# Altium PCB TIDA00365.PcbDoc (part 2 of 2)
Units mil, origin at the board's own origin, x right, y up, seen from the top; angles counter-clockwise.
Board outline 2520 x 2690 mil, 4 copper layers (Top Layer, Mid Layer, GND Layer, Bottom Layer), stack 69.2 mil thick; 171 components, 86 nets, 427 pads, 370 vias.
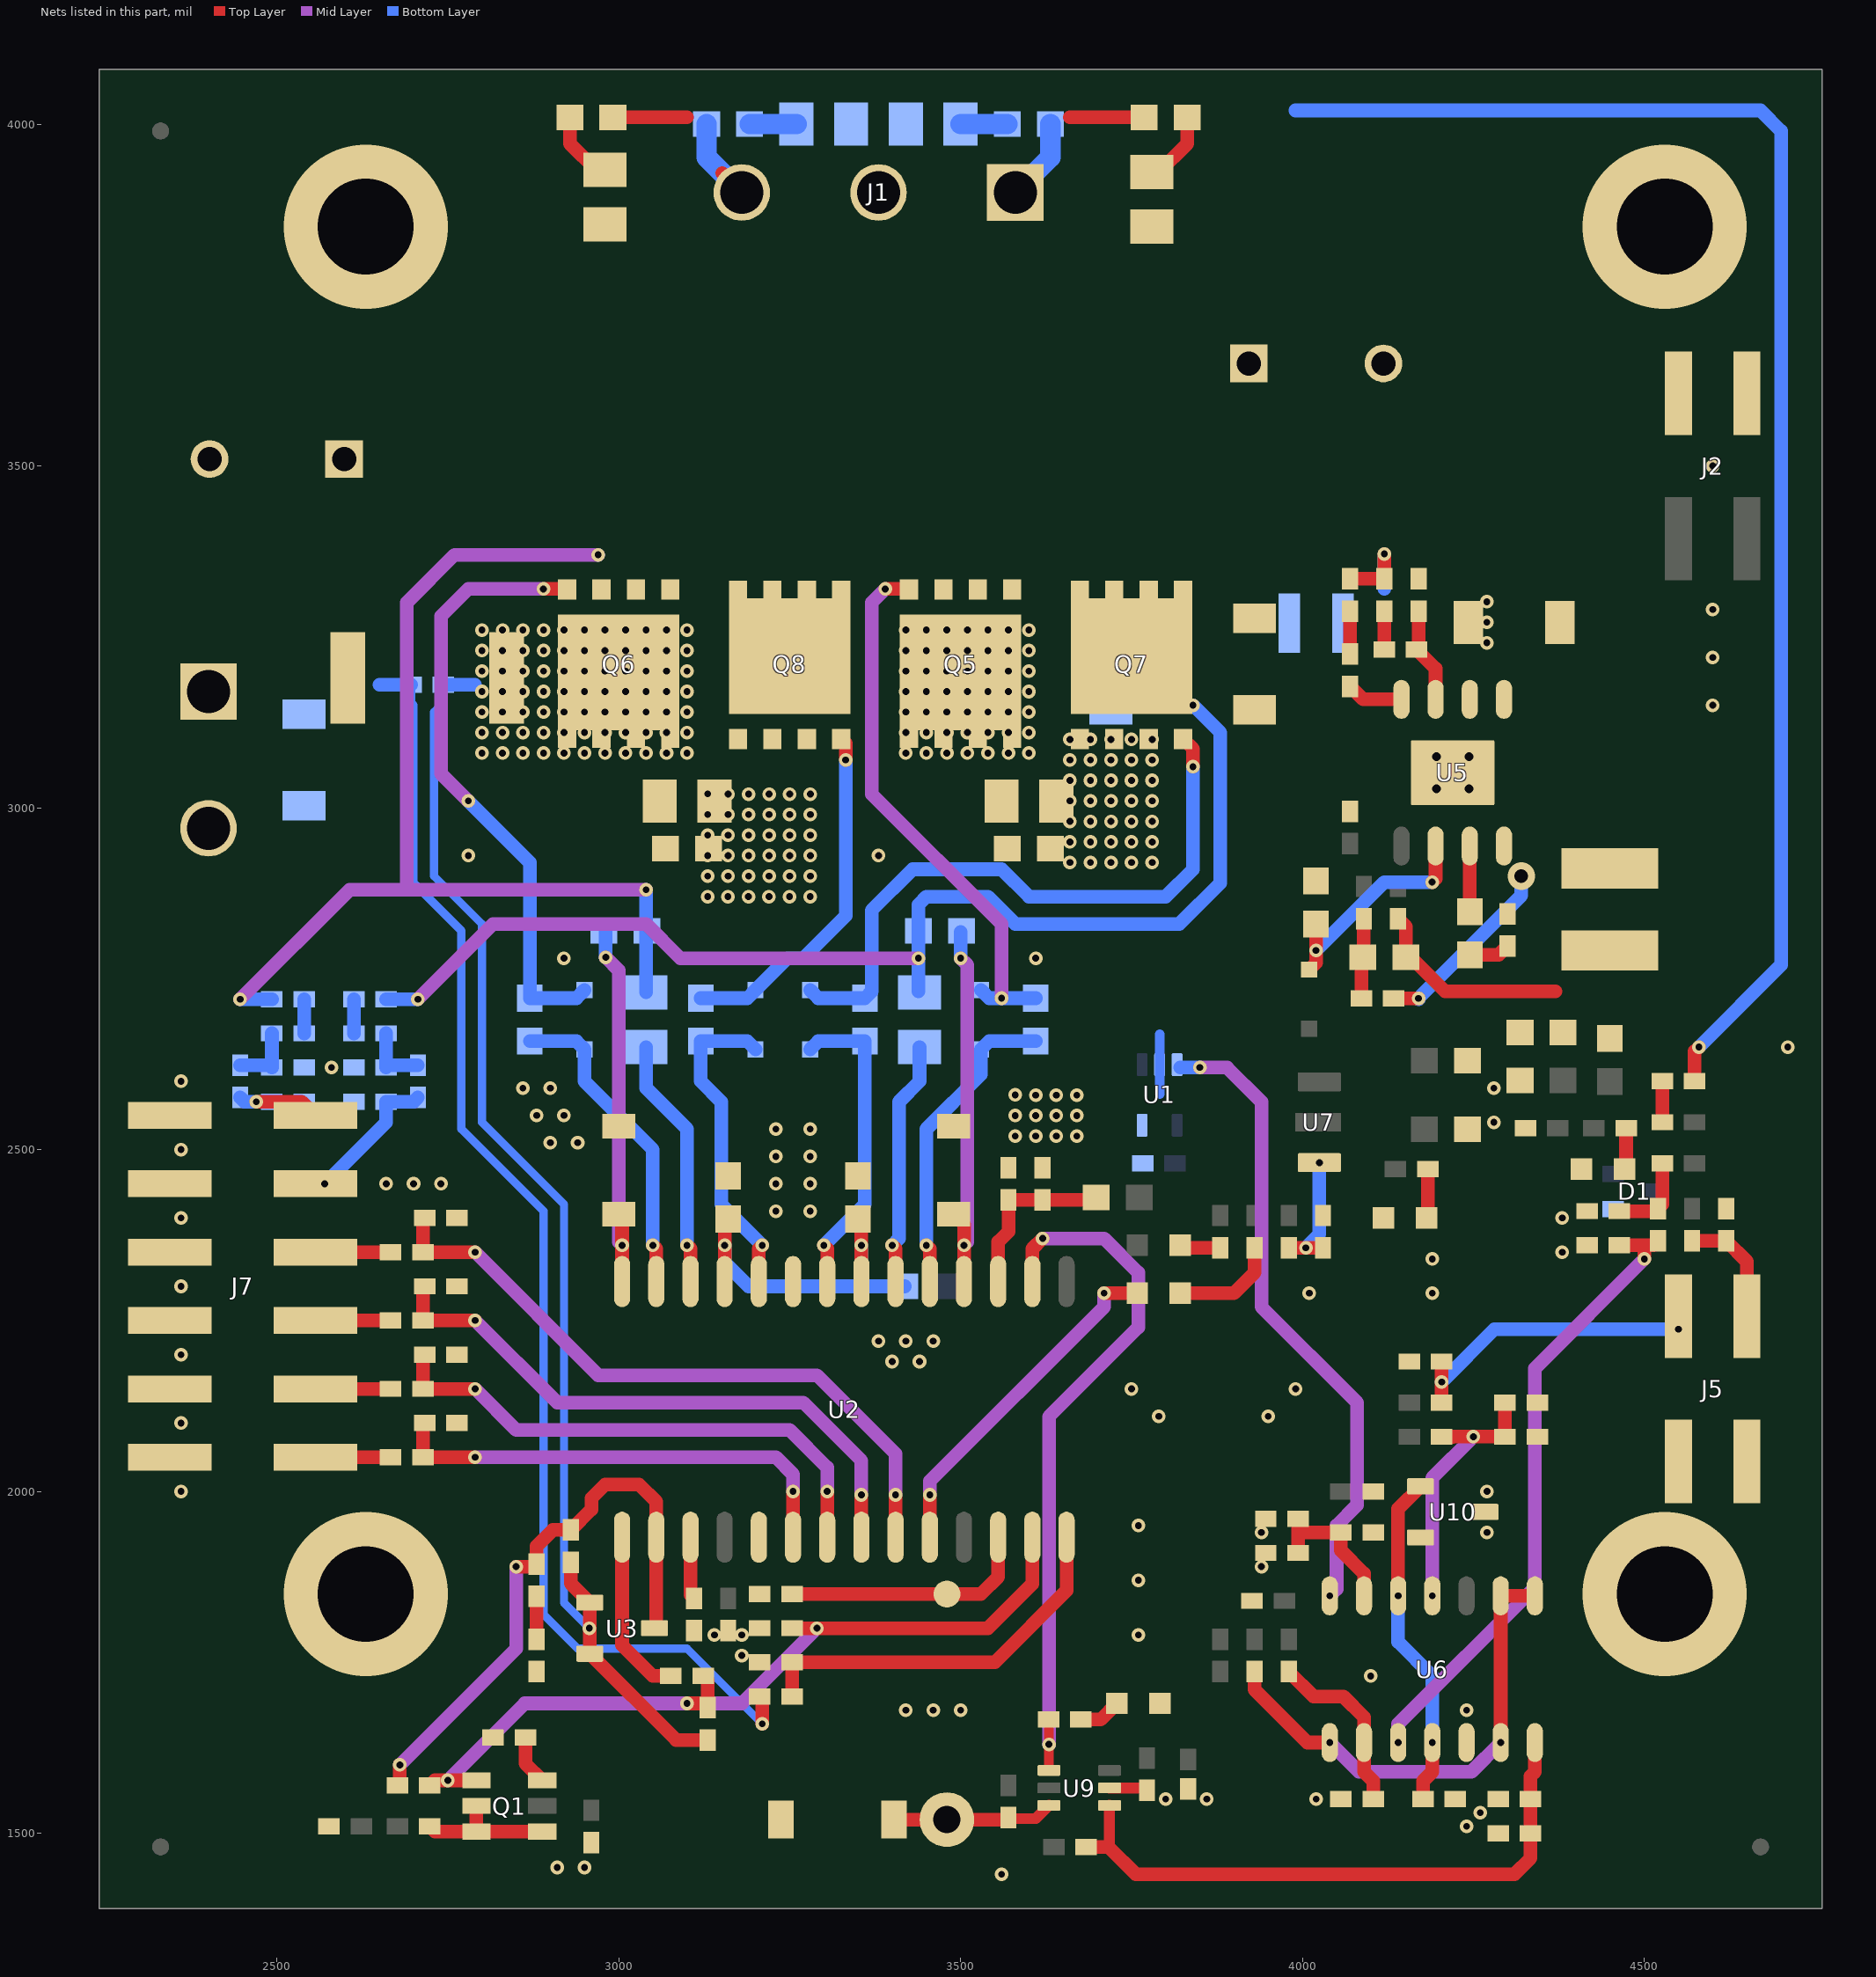
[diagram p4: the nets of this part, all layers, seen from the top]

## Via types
v1: diameter 20, hole 10, Top Layer to Bottom Layer, 355 vias
v2: diameter 40, hole 20, Top Layer to Bottom Layer, 7 vias
v3: diameter 25.98, hole 12.99, Top Layer to Bottom Layer, tented top, 4 vias
v4: diameter 240, hole 140, Top Layer to Bottom Layer, 4 vias

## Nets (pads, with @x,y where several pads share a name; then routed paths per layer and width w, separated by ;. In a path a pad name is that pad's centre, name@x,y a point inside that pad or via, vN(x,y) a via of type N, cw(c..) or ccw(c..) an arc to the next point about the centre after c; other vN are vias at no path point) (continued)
GND: 3.3V.1 12V.1 C1.2 C2.2 C3.2 C4.1 C5.2 C6.2 C8.1 C9.2 C10.2 C11.2 C12.2 C13.2 C14.2 C15.2 C16.2 C17.2 C18.2 C21.2 C22.1 C23.2 C24.2 C26.2 C28.2 C32.2 C33.2 C34.2 C39.2 C41.2 C50.2 C57.2 C62.2 C64.2 C66.1 C67.1 C68.1 C69.1 C70.2 C71.2 C72.2 C73.2 CLR_FLT.1 D1.1 D6.2 D9.2 D10.2 J1.2 J2.1 J2.3 J4.2 J5.1 J5.3 J7.1 J7.3 J7.5 J7.7 J7.9 J7.11 Q7.1 Q7.2 Q7.3 Q8.1 Q8.2 Q8.3 R6.1 R8.1 R12.1 R23.2 R24.1 R28.2 R29.2 R72.1 R73.1 R82.1 R92.1 R97.1 R98.1 R102.1 R103.1 R113.1 R118.1 TRIP.1 U1.2 U1.5 U2.5 U2.23 U5.1 U5.9 U6.12 U9.2 U10.3 | length 145
  Top Layer w16: U9.2@3717.91,1566.38 3770,1566.38 C9.2@3773.62,1562.76
  Bottom Layer w14: 3791.11,2581.11 U1.2@3791.11,2624.24 3791.11,2668.89
  other v1: 3560,1440 2910,1450 2950,1450 4240,1510 4260,1530 3800,1550 3860,1550 4020,1550 3420,1680 3460,1680 3500,1680 4240,1680 4100,1730 3180,1760 3140,1790 3180,1790 3760,1790 3760,1870 3940,1890 3940,1940 4270,1940 3760,1950 2360,2000 4270,2000 2360,2100 3790,2110 3950,2110 3750,2150 3990,2150 3400,2190 3440,2190 2360,2200 3380,2220 3420,2220 3460,2220 4010,2290 4190,2290 2360,2300 4190,2340 4380,2350 2360,2400 4380,2400 3230,2410 3280,2410 2660,2450 2700,2450 2740,2450 3230,2450 3280,2450 3230,2490 3280,2490 2360,2500 2900,2510 2940,2510 3580,2519.74 3609.98,2519.74 3639.98,2519.74 3669.98,2519.74 3230,2530 3280,2530 4280,2540 2880,2550 2920,2550 3580,2549.74 3610,2549.74 3640,2549.74 3670,2549.74 3580,2580 3610,2579.74 3640,2579.74 3670,2579.74 2860,2590 2900,2590 4280,2590 2360,2600 2580,2620 4710,2650 2920,2780 3610,2780 3130,2870 3159.74,2870 3189.74,2870 3219.74,2870 3249.74,2870 3280,2870 3130,2900 3160,2900 3190,2900 3220,2900 3250,2900 3280.26,2900 3660,2920 3689.98,2920 3719.98,2920 3749.98,2920 3780.24,2920 2780,2930 3130,2930 3159.98,2930 3189.98,2930 3219.98,2930 3249.98,2930 3280.24,2930 3380,2930 3660,2950 3689.98,2950 3719.98,2950 3749.98,2950 3780.24,2950 3130,2960 3159.98,2960 3189.98,2960 3219.98,2960 3249.98,2960 3280.24,2960 3660,2980 3690,2980 3720,2980 3750,2980 3780.26,2980 3130,2990 3160,2990 3190,2990 3220,2990 3250,2990 3280.26,2990 3660,3010 3690,3010 3720,3010 3750,3010 3780.26,3010 3130,3020.26 3160,3020 3190,3020 3220,3020 3250,3020 3280.26,3020 3660,3040 3690,3040 3720,3040 3750,3040 3780.26,3040 3660,3070 3690,3070 3720,3070 3750,3070 3780.26,3070 3660,3100 3690,3100 3720,3100 3750,3100 3780.26,3100 4600,3150 4600,3220 4600,3290 4600,3500
  other v3: 4196.18,3027.68 4243.43,3027.68 4196.18,3074.92 4243.43,3074.92
  other v4: 2630,1850 4530,1850 2630,3850 4530,3850
HS_3: C71.1 R3.2 U2.7 | length 792.2
  Top Layer w20: C71.1@2716.38,2200 2713.62,2197.24 R3.2@2713.62,2150 v1(2790,2150) ; U2.7@3305,1932.99 v1(3305,2000)
  Mid Layer w20: v1(2790,2150) 2850,2090 3250,2090 3305,2035 v1(3305,2000)
HS_4: C72.1 R4.2 U2.8 | length 889.4
  Top Layer w20: C72.1@2716.38,2300 2713.62,2297.24 R4.2@2713.62,2250 v1(2790,2250) ; U2.8@3355,1932.99 v1(3355,1995)
  Mid Layer w20: v1(2790,2250) 2910,2130 3270,2130 3355,2045 v1(3355,1995)
HS_BOOT_3: C19.1 U2.26 | length 369.9
  Top Layer w20: v1(3100,2360) 3105,2355 U2.26@3105,2307.01
  Bottom Layer w20: C19.1@3040,2650 3040,2590 3100,2530 v1(3100,2360)
HS_BOOT_4: C20.1 U2.20 | length 361.6
  Top Layer w20: v1(3400,2360) 3405,2355 U2.20@3405,2307.01
  Bottom Layer w20: v1(3400,2360) 3410,2370 3410,2570 3440,2600 C20.1@3440,2650
HS_CSN_2: C7.2 C11.1 C12.1 C14.1 C21.1 C25.1 Q5.5 Q5.6 Q5.7 Q5.8 Q5.9 Q6.5 Q6.6 Q6.7 Q6.8 Q6.9 R53.2 R64.1 U3.1 U3.2 | length 1895.9
  Top Layer w20: C25.1@2930,1896.38 2930,1865.16 U3.1@2957.76,1837.4 U3.2@2957.76,1762.6 3083.98,1636.38 R53.2@3130,1636.38
  Bottom Layer w12: C7.2@2743.62,3180 2743.62,3153.62 2730,3140 2730,2900 2800,2830 2800,2540 2920,2420 2920,1837.09 v1(2957.09,1800)
  Bottom Layer w20: C7.2@2743.62,3180 2790,3180
  other v1: 2800,3080 2830,3080 2860,3080 2890,3080 2920,3080 2950,3080 2980,3080 3010,3080 3040,3080 3070,3080 3100,3080 3420,3080 3450,3080 3480,3080 3510,3080 3540,3080 3570,3080 3600,3080 2800,3110 2830,3110 2860,3110 2890,3110 2920,3110 2950,3110 2980,3110 3010,3110 3040,3110 3070,3110 3100,3110 3420,3110 3450,3110 3480,3110 3510,3110 3540,3110 3570,3110 3600,3110 2800,3140 2830,3140 2860,3140 2890,3140 2920,3140 2950,3140 2980,3140 3010,3140 3040,3140 3070,3140 3100,3140 3420,3140 3450,3140 3480,3140 3510,3140 3540,3140 3570,3140 3600,3140 2800,3170 2830,3170 2860,3170 2890,3170 2920,3170 2950,3170 2980,3170 3010,3170 3040,3170 3070,3170 3100,3170 3420,3170 3450,3170 3480,3170 3510,3170 3540,3170 3570,3170 3600,3170 2800,3200 2830,3200 2860,3200 2890,3200 2920,3200 2950,3200 2980,3200 3010,3200 3040,3200 3070,3200 3100,3200 3420,3200 3450,3200 3480,3200 3510,3200 3540,3200 3570,3200 3600,3200 2800,3230 2830,3230 2860,3230 2890,3230 2920,3230 2950,3230 2980,3230 3010,3230 3040,3230 3070,3230 3100,3230 3420,3230 3450,3230 3480,3230 3510,3230 3540,3230 3570,3230 3600,3230 2800,3260 2830,3260 2860,3260 2890,3260 2920,3260 2950,3260 2980,3260 3010,3260 3040,3260 3070,3260 3100,3260 3420,3260 3450,3260 3480,3260 3510,3260 3540,3260 3570,3260 3600,3260
HS_CSP_2: C5.1 C7.1 C15.1 C16.1 C17.1 C26.1 J4.1 L2.1 R21.2 R51.2 R64.2 R95.2 R96.2 | length 4074
  Top Layer w20: v1(3210,1660) R51.2@3210,1696.38 ; R21.2@4573.62,2600 4573.62,2643.62 v1(4580,2650)
  Bottom Layer w12: C7.1@2696.38,3180 2696.38,3153.62 2700,3150 2700,2890 2770,2820 2770,2530 2890,2410 2890,1820 2940,1770 3100,1770 v1(3210,1660)
  Bottom Layer w20: 2650,3180 C7.1@2696.38,3180 ; 3990,4020 4670,4020 4700,3990 4700,2770 v1(4580,2650)
HS_GATE_3: D8.1 R74.1 U2.27 | length 468.1
  Top Layer w20: v1(3050,2360) 3055,2355 U2.27@3055,2307.01
  Bottom Layer w20: R74.1@2870,2658.5 2938.19,2658.5 D8.1@2950,2646.69 2950,2600 3050,2500 v1(3050,2360)
HS_GATE_4: D4.1 R58.1 U2.19 | length 459.8
  Top Layer w20: v1(3450,2360) 3455,2355 U2.19@3455,2307.01
  Bottom Layer w20: v1(3450,2360) 3450,2530 3530,2610 D4.1@3530,2646.69 3541.81,2658.5 R58.1@3610,2658.5
HS_PHASE_3: D9.1 R61.1 U2.28 | length 567.9
  Top Layer w20: D9.1@3000,2405.53 3005,2400.53 v1(3005,2360) U2.28@3005,2307.01
  Mid Layer w20: v1(2981.11,2781.3) 3000,2762.41 3000,2365 v1(3005,2360)
  Bottom Layer w20: v1(2981.11,2781.3) R61.1@2981.11,2817.39
HS_PHASE_4: D10.1 R62.1 U2.18 | length 569.5
  Top Layer w20: D10.1@3490,2405.53 3505,2390.53 v1(3505,2360) U2.18@3505,2307.01
  Mid Layer w20: v1(3500,2780) 3510,2770 3510,2365 v1(3505,2360)
  Bottom Layer w20: v1(3500,2780) R62.1@3500,2818.5
IIN_2: R73.2 U2.3 | length 84.4
  Top Layer w20: R73.2@3105,1848.62 U2.3@3105,1932.99
IOUT_2: I_CS.1 R72.2 U2.12 | length 369.7
  Top Layer w20: R72.2@3253.62,1850 3530,1850 3555,1875 U2.12@3555,1932.99
LS_3: C70.1 R2.2 U2.6 | length 694.9
  Top Layer w20: C70.1@2716.38,2100 2713.62,2097.24 R2.2@2713.62,2050 v1(2790,2050) ; U2.6@3255,1932.99 v1(3255,2000)
  Mid Layer w20: v1(2790,2050) 3230,2050 3255,2025 v1(3255,2000)
LS_4: C73.1 R5.2 U2.9 | length 986.7
  Top Layer w20: C73.1@2716.38,2400 2713.62,2397.24 R5.2@2713.62,2350 v1(2790,2350) ; U2.9@3405,1932.99 v1(3405,1995)
  Mid Layer w20: v1(2790,2350) 2970,2170 3290,2170 3405,2055 v1(3405,1995)
LS_GATE_3: D5.1 R67.1 U2.24 | length 475.9
  Top Layer w20: U2.24@3205,2307.01 3205,2355.29 3205.29,2355.29 v1(3210,2360)
  Bottom Layer w20: D5.1@3200,2646.69 3188.19,2658.5 R67.1@3120,2658.5 3120,2600 3150,2570 3150,2420 v1(3210,2360)
LS_GATE_4: D13.1 R68.2 U2.22 | length 463.3
  Top Layer w20: v1(3300,2360) 3305,2355 U2.22@3305,2307.01
  Bottom Layer w20: D13.1@3280,2646.69 3291.81,2658.5 R68.2@3360,2658.5 3360,2420 v1(3300,2360)
Net3.3V_2: 3.3V.2 R25.1 | length 66.4
  Top Layer w20: 3.3V.2@4183.43,2404.92 R25.1@4183.43,2471.3
Net12V_2: 12V.2 R77.1 | length 60.9
  Top Layer w20: 12V.2@4471.3,2471.3 4473.43,2473.43 R77.1@4473.43,2531.3
NetC2_1: C2.1 C6.1 R10.1 U2.17 | length 255.6
  Top Layer w20: U2.17@3555,2307.01 3555,2365 3570,2380 C2.1@3570,2426.38 C6.1@3620,2426.38 3694.88,2426.38 R10.1@3698.5,2430
NetC4_2: C4.2 C8.2 R50.1 U2.21 U2.25 | length 545.1
  Top Layer w20: U2.25@3155,2307.01 v1(3155,2360) 3155,2393.5 C4.2@3160,2398.5 ; C8.2@3350,2398.5 3355,2393.5 v1(3355,2360) U2.21@3355,2307.01
  Bottom Layer w20: v1(3155,2360) 3155,2335 3190,2300 R50.1@3418.5,2300 ; 3355,2305 v1(3355,2360)
NetC10_1: C10.1 R85.2 R118.2 U6.4 | length 385.1
  Top Layer w20: 4220.39,2079.35 4219.74,2080 v1(4250,2080) R118.2@4296.38,2080 C10.1@4296.38,2130
  Mid Layer w20: v1(4190,1847.28) 4190,2020 v1(4250,2080)
NetC13_1: C13.1 R17.1 R24.2 U6.14 U9.1 | length 908.2
  Top Layer w16: 3717.91,1478.46 U9.1@3717.91,1540.79
  Top Layer w20: R17.1@3683.62,1480 3716.38,1480 ; 3717.91,1478.46 3756.38,1440 4310,1440 4333.62,1463.62 R24.2@4333.62,1500 C13.1@4333.62,1550 4333.62,1583.62 4340,1590 U6.14@4340,1632.72
NetC27_1: C27.1 R28.1 | length 68.5
  Bottom Layer w30: C27.1@3191.5,4000 R28.1@3260,4000
NetC28_1: C28.1 C36.1 L5.2 R78.1 R125.2 | length 300.4
  Top Layer w20: R125.2@4139.8,2837.68 4151.3,2826.18 C36.1@4151.3,2781.3 4158.7,2781.3 4208.7,2731.3 4369.8,2731.3
NetC29_1: C29.1 R29.1 | length 68.5
  Bottom Layer w30: R29.1@3500,4000 C29.1@3568.5,4000
NetC32_1: C32.1 L2.2 R79.1 R126.1 U5.2 | length 137.5
  Top Layer w20: R79.1@4069.8,3334.92 R126.1@4119.8,3334.92 v1(4119.8,3371.3)
  Bottom Layer w20: 4119.8,3320.2 v1(4119.8,3371.3)
  other v1: 4269.8,3241.3 4269.8,3271.3 4269.8,3301.3
NetC34_1: C34.1 D3.1 U5.6 | length 336.7
  Top Layer w20: D3.1@4010,2763.31 4019.8,2773.11 v1(4019.8,2791.38) C34.1@4019.8,2829.8 ; v1(4189.8,2891.3) 4194.8,2896.3 U5.6@4194.8,2944.02
  Bottom Layer w20: v1(4019.8,2791.38) 4119.73,2891.3 v1(4189.8,2891.3)
NetC36_2: C36.2 C40.1 R76.2 | length 117.9
  Top Layer w20: R76.2@4086.18,2721.3 4086.18,2779.17 C36.2@4088.31,2781.3 4089.8,2782.79 C40.1@4089.8,2837.68
NetC37_1: C37.1 U5.7 | length 96.2
  Top Layer w20: C37.1@4244.8,2847.8 U5.7@4244.8,2944.02
NetC37_2: C37.2 R101.1 | length 60.3
  Top Layer w20: C37.2@4244.8,2784.8 4286.93,2784.8 R101.1@4299.8,2797.68
NetC51_1: C51.1 R95.1 | length 105.9
  Top Layer w20: C51.1@2928.5,4010 2928.5,3971.5 2966.8,3933.2 R95.1@2980,3933.2
NetC52_1: C52.1 R96.1 | length 107.3
  Top Layer w20: R96.1@3780,3930 3790.19,3930 3831.5,3971.3 C52.1@3831.5,4010
NetC66_2: C66.2 J7.4 R36.1 | length 258.8
  Top Layer w20: J7.4@2537.5,2450 J7.4@2590,2450
  Bottom Layer w20: v1(2570,2450) 2660,2540 C66.2@2660,2570 2700,2570 R36.1@2706.38,2576.38
NetC67_2: C67.2 J7.2 R27.1 | length 143.6
  Top Layer w20: v1(2470,2570) 2536.3,2570 J7.2@2556.3,2550
  Bottom Layer w20: R27.1@2446.38,2576.38 2452.76,2570 v1(2470,2570) C67.2@2492.76,2570
NetC68_2: C68.2 J5.4 R16.1 | length 191.4
  Top Layer w20: R16.1@4570,2366.38 C68.2@4620,2366.38 4650,2336.38 J5.4@4650,2237.4
NetC69_2: C69.2 J5.2 R15.1 | length 438.4
  Top Layer w20: R15.1@4203.62,2130 v1(4203.62,2160) C69.2@4203.62,2190
  Bottom Layer w20: v1(4203.62,2160) 4281.02,2237.4 v1(4550,2237.4)
NetD4_2: D4.2 Q5.4 R58.2 | length 805.2
  Top Layer w20: v1(3389.96,3320) 3423.81,3320 Q5.4@3424.51,3319.3
  Mid Layer w20: v1(3389.96,3320) 3370,3300.04 3370,3020 3560,2830 3560,2731.5 v1(3560,2721.5)
  Bottom Layer w20: D4.2@3530,2733.31 3541.81,2721.5 v1(3560,2721.5) R58.2@3610,2721.5
NetD5_2: D5.2 Q8.4 R67.2 | length 523.3
  Top Layer w20: Q8.4@3325.49,3100.7 3331.97,3094.22 v1(3331.97,3070)
  Bottom Layer w20: R67.2@3120,2721.5 3188.19,2721.5 D5.2@3200,2733.31 3246.69,2780 3270,2780 3331.97,2841.97 v1(3331.97,3070)
NetD8_2: D8.2 Q6.4 R74.2 | length 898.6
  Top Layer w20: v1(2889.96,3320) 2923.81,3320 Q6.4@2924.51,3319.3
  Mid Layer w20: v1(2780,3010) 2740,3050 2740,3280 2780,3320 v1(2889.96,3320)
  Bottom Layer w20: v1(2780,3010) 2870,2920 R74.2@2870,2721.5 2938.19,2721.5 D8.2@2950,2733.31
NetD13_2: D13.2 Q7.4 R68.1 | length 942.2
  Top Layer w20: Q7.4@3825.49,3100.7 3840,3086.19 v1(3840,3060)
  Bottom Layer w20: D13.2@3280,2733.31 3291.81,2721.5 R68.1@3360,2721.5 3370,2731.5 3370,2850 3430,2910 3560,2910 3600,2870 3800,2870 3840,2910 v1(3840,3060)
NetFAULT_2: FAULT.2 R20.1 | length 60
  Top Layer w20: FAULT.2@3821.5,2360 3825.12,2356.38 R20.1@3880,2356.38
NetJ7_6: J7.6 R5.1 | length 128.9
  Top Layer w20: J7.6@2537.5,2350 R5.1@2666.38,2350
NetJ7_8: J7.8 R4.1 | length 128.9
  Top Layer w20: J7.8@2537.5,2250 R4.1@2666.38,2250
NetJ7_10: J7.10 R3.1 | length 128.9
  Top Layer w20: J7.10@2537.5,2150 R3.1@2666.38,2150
NetJ7_12: J7.12 R2.1 | length 128.9
  Top Layer w20: J7.12@2537.5,2050 R2.1@2666.38,2050
NetL5_1: L5.1 R76.1 R101.2 U5.8 | length 278.1
  Top Layer w20: R76.1@4133.43,2721.3 v1(4169.8,2721.3)
  Bottom Layer w20: v1(4169.8,2721.3) 4320,2871.5 v2(4320,2900) ; v1@4170,2720 v1@4170.55,2720.55
NetPGOOD_2: PGOOD.2 R14.1 | length 157.3
  Top Layer w20: PGOOD.2@3821.5,2290 3900,2290 3930,2320 R14.1@3930,2356.38
NetQ1_2: Q1.2 Q1.3 Q1.4 R11.1 | length 205.1
  Top Layer w20: R11.1@2723.62,1510 2731.02,1502.6 Q1.3@2791.77,1502.6 ; Q1.2@2791.77,1540 Q1.3@2791.77,1502.6 ; Q1.4@2888.23,1502.6 Q1.3@2791.77,1502.6
NetQ1_6: Q1.6 R12.2 | length 72.8
  Top Layer w20: R12.2@2863.62,1640 2863.62,1602.01 Q1.6@2888.23,1577.4
NetR1_1: R1.1 R6.2 U7.1 | length 182.8
  Top Layer w20: R1.1@3980,2356.38 v1(4005,2356.38) R6.2@4030,2356.38
  Bottom Layer w20: v1(4005,2356.38) 4024.8,2376.18 v1(4024.8,2480.94)
NetR18_2: R18.2 U6.1 U6.2 U6.8 U6.13 | length 718.3
  Top Layer w20: R18.2@3930,1736.38 3930,1710 4007.28,1632.72 v1(4040,1632.72) ; v1(4290,1632.72) U6.2@4290,1847.28 U6.1@4340,1847.28
  Mid Layer w20: v1(4040,1632.72) 4082.72,1590 4247.28,1590 v1(4290,1632.72)
NetR19_2: R19.2 R23.1 U6.9 | length 263.1
  Top Layer w20: R19.2@3980,1736.38 4016.38,1700 4060,1700 4090,1670 U6.9@4090,1632.72 4090,1590 4103.62,1576.38 R23.1@4103.62,1550
NetR21_1: R21.1 R81.2 | length 60
  Top Layer w20: R81.2@4526.38,2540 R21.1@4526.38,2600
NetR22_1: R22.1 R57.2 R113.2 | length 126.9
  Top Layer w20: R113.2@4463.62,2410 4516.38,2410 R57.2@4520,2413.62 4526.38,2420 R22.1@4526.38,2480
NetR27_2: R27.2 R91.1 R103.2 | length 92.8
  Bottom Layer w20: R27.2@2446.38,2623.62 R103.2@2489.13,2623.62 ; R103.2@2492.76,2620 R91.1@2492.76,2670
NetR35_1: R35.1 R83.2 | length 50
  Bottom Layer w20: R83.2@2612.76,2670 R35.1@2612.76,2720
NetR36_2: R36.2 R83.1 R102.2 | length 92.8
  Bottom Layer w20: R102.2@2660,2620 R83.1@2660,2670 ; R102.2@2663.62,2623.62 R36.2@2706.38,2623.62
NetR40_1: R40.1 R91.2 | length 50
  Bottom Layer w20: R91.2@2540,2670 R40.1@2540,2720
NetR66_2: R66.2 TRIP.2 | length 62.4
  Top Layer w20: R66.2@3675.91,1666.38 3704.88,1666.38 TRIP.2@3728.5,1690
NetR71_2: R71.2 R97.2 | length 62.8
  Top Layer w20: R97.2@2880,1783.62 R71.2@2880,1846.38
NetR79_2: R79.2 R80.1 | length 62.8
  Top Layer w20: R80.1@4069.8,3224.92 R79.2@4069.8,3287.68
NetR80_2: R80.2 U5.4 | length 82.9
  Top Layer w20: R80.2@4069.8,3177.68 4088.9,3158.58 U5.4@4144.8,3158.58
NetR82_2: R82.2 R93.2 U5.3 | length 141.7
  Top Layer w20: R82.2@4169.8,3287.68 4169.8,3234.06 R93.2@4167.05,3231.3 4194.8,3203.54 U5.3@4194.8,3158.58
NetR93_1: R93.1 R126.2 | length 56.4
  Top Layer w20: R93.1@4119.8,3231.3 R126.2@4119.8,3287.68
NetU1_3: U1.3 U6.7 | length 936.8
  Mid Layer w20: v1(3850,2620) 3890,2620 3940,2570 3940,2270 4080,2130 4080,1980 4050,1950 4050,1857.28 v1(4040,1847.28)
  Bottom Layer w20: U1.3@3821.23,2620 v1(3850,2620)
OVS: R66.1 U2.16 U9.4 | length 1048.5
  Top Layer w14: U9.4@3629.33,1591.97 v1(3629.33,1630) R66.1@3629.33,1666.38
  Top Layer w20: U2.16@3605,2307.01 3605,2355 v1(3620,2370)
  Mid Layer w20: v1(3620,2370) 3710,2370 3760,2320 3760,2240 3629.33,2109.33 v1(3629.33,1630)
PGOOD2: PGOOD.1 U2.10 | length 511.1
  Top Layer w20: U2.10@3455,1932.99 v1(3455,1995) ; v1(3710,2290) PGOOD.1@3758.5,2290
  Mid Layer w20: v1(3455,1995) 3455,2015 3710,2270 v1(3710,2290)
PHASEB+: C19.2 C27.2 C51.2 J1.3 Q6.1 Q6.2 Q6.3 Q8.5 Q8.6 Q8.7 Q8.8 Q8.9 R40.2 R61.2 | length 1854.6
  Top Layer w20: C51.2@2991.5,4010 3100.02,4010 ; J1.3@3151.5,3928.5 J1.3@3180,3900
  Mid Layer w20: v1(2446.38,2720) 2606.38,2880 v1(3040,2880) ; 2690,2880 2690,3300 2760,3370 v1(2970,3370)
  Bottom Layer w20: v1(2446.38,2720) R40.2@2492.76,2720 ; C19.2@3040,2730 3040,2818.5 R61.2@3041.5,2820 ; R61.2@3040,2821.5 v1(3040,2880)
  Bottom Layer w30: C27.2@3128.5,4000 3128.5,3951.5 J1.3@3180,3900
PHASEB-: C20.2 C29.2 C52.2 J1.1 Q5.1 Q5.2 Q5.3 Q7.5 Q7.6 Q7.7 Q7.8 Q7.9 R35.2 R62.2 | length 2006.2
  Top Layer w20: J1.1@3580,3900 J1.1@3608.5,3928.5 ; 3659.98,4010 C52.2@3768.5,4010
  Mid Layer w20: v1(2706.38,2720) 2816.38,2830 3040,2830 3090,2780 v1(3438.5,2780)
  Bottom Layer w20: R35.2@2660,2720 v1(2706.38,2720) ; C20.2@3438.5,2731.5 v1(3438.5,2780) R62.2@3438.5,2820 3438.5,2858.5 3450,2870 3540,2870 3580,2830 3820,2830 3880,2890 3880,3110 v1(3840,3150)
  Bottom Layer w30: J1.1@3580,3900 3631.5,3951.5 C29.2@3631.5,4000
PROT_VTH: C41.1 R7.2 R26.1 U6.5 U6.11 U10.1 U10.2 | length 500
  Top Layer w20: v1(4140,1847.28) 4140,1974.65 U10.1@4172.76,2007.4 ; C41.1@4176.38,1550 4176.38,1576.38 4190,1590 v1(4190,1632.72)
  Bottom Layer w20: v1@4140,1850 v1(4140,1847.28) 4140,1780 4190,1730 v1(4190,1632.72)
RESET: CLR_FLT.2 R49.1 TP1.1 U9.6 | length 235.3
  Top Layer w16: R49.1@3571.38,1521.38 3609.92,1521.38 U9.6@3629.33,1540.79
  Top Layer w20: CLR_FLT.2@3402.68,1520 TP1.1@3480,1520 3570,1520 R49.1@3571.38,1521.38
SIA_2: R69.1 U2.1 | length 248
  Top Layer w20: U2.1@3005,1932.99 3005,1775 3050,1730 R69.1@3076.38,1730
SIB_2: C22.2 R51.1 U2.14 | length 572.9
  Top Layer w20: R51.1@3253.62,1700 C22.2@3253.62,1750 3550,1750 3655,1855 U2.14@3655,1932.99
SOA_2: C25.2 R9.1 R71.1 U2.2 U3.3 | length 868.2
  Top Layer w20: R9.1@2676.38,1570 2680,1573.62 v1(2680,1600) ; v1(2850,1890) 2876.38,1890 R71.1@2880,1893.62 2880,1920 2903.62,1943.62 C25.2@2930,1943.62 2960,1973.62 2960,1990 2980,2010 3030,2010 3055,1985 U2.2@3055,1932.99 3055,1802.76 U3.3@3052.24,1800
  Mid Layer w20: v1(2680,1600) 2850,1770 v1(2850,1890)
SOB_2: C23.1 Q1.1 R9.2 R53.1 R69.2 U2.13 | length 1231.4
  Top Layer w20: R9.2@2723.62,1570 2731.02,1577.4 v1(2750,1577.4) Q1.1@2791.77,1577.4 ; v1(3100,1690) 3123.62,1690 R53.1@3130,1683.62 3130,1723.62 R69.2@3123.62,1730 ; C23.1@3253.62,1800 v1(3290,1800) 3540,1800 3605,1865 U2.13@3605,1932.99
  Mid Layer w20: v1(2750,1577.4) 2862.6,1690 v1(3100,1690) 3180,1690 v1(3290,1800)
TEMP_VTH: C3.1 R7.1 R8.2 U6.6 | length 203
  Top Layer w20: R8.2@3993.62,1910 3993.62,1940 ; C3.1@3993.62,1960 3993.62,1940 ; 4040,1940 3993.62,1940 ; R7.1@4056.38,1940 4056.38,1913.62 4090,1880 U6.6@4090,1847.28
VBUS_SENSE: C33.1 R57.1 U6.10 | length 926.4
  Top Layer w20: C33.1@4463.62,2360 R57.1@4513.62,2360 ; v1(4500,2340) 4500,2360
  Mid Layer w20: v1(4140,1632.72) 4140,1660 4340,1860 4340,2180 v1(4500,2340)
pads on no net: FID1.1 FID2.1 FID3.1 FID4.1 FID5.1 FID6.1 U1.1

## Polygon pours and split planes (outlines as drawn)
HS_CSP_2 on Top Layer "HS_CSP_2_L01_P058" (solid, remove dead copper, pour order 58): 2270,3080 2660,3080 2660,3190 2690,3220 3550,3220 3700,3220 4000,3220 4010,3230 4010,4050 2270,4050
+12V on Top Layer "+12V_L01_P074" (solid, remove dead copper, pour order 74): 3995.24,2588.39 4200,2588.39 4200,2686.16 3995.24,2686.16
NetC32_1 on Top Layer "NETC32_1_L01_P052" (solid, remove dead copper, pour order 52): 4239.8,3131.3 4229.8,3141.3 4229.8,3210.2 4209.8,3230.2 4209.8,3311.3 4229.8,3331.3 4268.7,3331.3 4289.8,3310.2 4289.8,3239.8 4259.8,3209.8 4259.8,3141.3 4249.8,3131.3
NetL5_1 on Top Layer "NETL5_1_L01_P067" (solid, remove dead copper, pour order 67): 4289.8,2831.3 4309.8,2831.3 4309.8,2861.3 4319.8,2871.3 4359.8,2871.3 4559.8,2871.3 4559.8,2971.3 4549.8,2981.3 4289.8,2981.3 4279.8,2971.3 4279.8,2881.3 4289.8,2871.3
NetC28_1 on Top Layer "NETC28_1_L01_P073" (solid, remove dead copper, pour order 73): 4339.8,2831.3 4339.8,2741.3 4359.8,2721.3 4359.8,2651.3 4419.8,2651.3 4429.8,2641.3 4479.8,2641.3 4559.8,2721.3 4559.8,2831.3
+3V3 on Top Layer "+3V3_L01_P045" (solid, remove dead copper, pour order 45): 4120,2460 4120,2510 4100,2510 4100,2560 4150,2560 4200,2560 4200,2510 4160,2510 4150,2500 4150,2460
+12V on Top Layer "+12V_L01_P064" (solid, remove dead copper, pour order 64): 4359.8,2521.3 4359.8,2621.3 4469.8,2621.3 4469.8,2571.3 4449.8,2551.3 4449.8,2521.3
GND on Top Layer "GND_L01_P115" (solid, remove dead copper, pour order 115): 2270,1420 4730,1420 4730,4050 2270,4050
HS_CSN_2 on Top Layer "HS_CSN_2_L01_P057" (solid, remove dead copper, pour order 57): 2780,3280 3120,3280 3120,3100 3120,3060 3090,3060 3090,2920 2920,2920 2780,3060
HS_CSN_2 on Top Layer "HS_CSN_2_L01_P054" (solid, remove dead copper, pour order 54): 3400,3280 3620,3280 3620,3060 3590,3060 3590,2920 3450,2920 3400,2970 3400,3060
PHASEB+ on Top Layer "PHASEB+_L01_P056" (solid, remove dead copper, pour order 56): 2960,3300 3130,3300 3150,3280 3150,3140 3350,3140 3350,3830 3280,3900 3280,4050 3120,4050 3080,4010 3080,3780 2960,3660
PHASEB- on Top Layer "PHASEB-_L01_P055" (solid, remove dead copper, pour order 55): 3410,3830 3480,3900 3480,4050 3640,4050 3680,4010 3680,3570 3850,3400 3850,3140 3650,3140 3650,3280 3630,3300 3460,3300 3460,3370 3410,3420
PROT_VTH on Top Layer "PROT_VTH_L01_P044" (solid, remove dead copper, pour order 44): 4090,1930 4090,2020 4200,2020 4200,1920 4160,1920 4140,1900 4110,1930
GND on Bottom Layer "GND_L04_P043" (solid, remove dead copper, pour order 43): 3450,4050 3450,3950 3470,3930 3470,3860 3450,3840 3310,3840 3290,3860 3290,3930 3310,3950 3310,4050
HS_CSN_2 on Bottom Layer "HS_CSN_2_L04_P053" (solid, remove dead copper, pour order 53): 3620,3280 3620,3060 2780,3060 2780,3280
NetC32_1 on Bottom Layer "NETC32_1_L04_P065" (solid, remove dead copper, pour order 65): 4040,3210 4030,3220 4030,3320 4040,3330 4270,3330 4290,3310 4290,3230 4270,3210
GND on Bottom Layer "GND_L04_P077" (solid, remove dead copper, pour order 77): 2270,1420 4730,1420 4730,4050 2270,4050
HS_CSP_2 on Bottom Layer "HS_CSP_2_L04_P063" (solid, remove dead copper, pour order 63): 2270,3080 2660,3080 2660,3190 2660,3220 2690,3220 3550,3220 3700,3220 4000,3220 4010,3220 4010,3230 4010,4050 2270,4050
GND on Mid Layer "GND_L02_P079" (solid, remove dead copper, pour order 79): 2270,1420 4730,1420 4730,4050 2270,4050
HS_CSN_2 on Mid Layer "HS_CSN_2_L02_P051" (solid, remove dead copper, pour order 51): 2780,3270 2790,3280 3110,3280 3120,3270 3120,3070 3110,3060 2790,3060 2780,3070
HS_CSN_2 on Mid Layer "HS_CSN_2_L02_P050" (solid, remove dead copper, pour order 50): 3610,3060 3620,3070 3620,3263.51 3620,3270 3610,3280 3410,3280 3400,3270 3400,3070 3410,3060
GND on GND Layer "GND_L03_P078" (solid, remove dead copper, pour order 78): 2270,1420 4730,1420 4730,4050 2270,4050
HS_CSN_2 on GND Layer "HS_CSN_2_L03_P049" (solid, remove dead copper, pour order 49): 2780,3270 2790,3280 3110,3280 3120,3270 3120,3070 3110,3060 2790,3060 2780,3070
HS_CSN_2 on GND Layer "HS_CSN_2_L03_P048" (solid, remove dead copper, pour order 48): 3610,3060 3620,3070 3620,3263.51 3620,3270 3610,3280 3410,3280 3400,3270 3400,3070 3410,3060
no net on Bottom Paste "Bottom Paste-No Net" (solid): 4280,3110 4160,3110 4160,2990 4280,2990
HS_CSN_2 on Bottom Paste "NONET_L04_P125" (solid, pour order 47): 3620,3280 3620,3060 2780,3060 2780,3280
no net on Solder Side "Solder Side-No Net" (solid): 4280,2990 4160,2990 4160,3110 4280,3110
HS_CSN_2 on Solder Side "NONET_L04_P127" (solid, pour order 46): 3620,3280 3620,3060 2780,3060 2780,3280

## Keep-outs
Keep-Out Layer:
  lines w10: 2230,1380 2230,4090 4770,4090 4770,1380 2230,1380
  text ".Layer_Name" at 577,-858.49 h60

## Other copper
Top Layer:
  pour cut-out: 4590,2174.96 4610,2174.96 4610,2190 4590,2190
  pour cut-out: 3360,3830 3400,3830 3400,3820 3360,3820
  pour cut-out: 3031.5,3888.2 3059.61,3888.2 3059.61,3909.61 3060,3910 3030,3910
  pour cut-out: 3728.5,3885 3700.39,3885 3700,3885.39 3700,3910 3720,3910 3730,3900
  text ".Layer_Name" at 577,-858.49 h60
Bottom Layer:
  pour cut-out: 3280,3850 3200,3850 3210,3860 3280,3860
  pour cut-out: 3530,3840 3470,3840 3480,3850 3530,3850
  pour cut-out: 3090,4030 3090,4060 3100,4060 3100,4030
  pour cut-out: 3670,4030 3670,4060 3660,4060 3660,4030
  pour cut-out: 3220,2620 3225.12,2614.88 3254.88,2614.88 3260,2620
  text ".Layer_Name" at 577,-858.49 h60

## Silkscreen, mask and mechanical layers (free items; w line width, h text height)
Top Overlay:
  text "Full-Bridge / Power Stage" at 4460,3420 h50 r90
  text "+" at 2270,3280 h72.83
  text "+3.3V /  / +12V" at 4800,3130 h40 r90
  text "-" at 2270,2780 h72.83
  text "TIDA-00365 Rev.E1" at 4700,2480 h40 r90
  text "CS / DC_Link" at 4620,2030 h40 r90
  text "PH+ / PH- / LS_B / HS_B / HS_A / LS_A" at 2310,1530 h40
  text ".Layer_Name" at 577,-858.49 h60
Bottom Overlay:
  text ".Layer_Name" at 577,-858.49 h60
Top Paste:
  text ".Layer_Name" at 577,-858.49 h60
Bottom Paste:
  text ".Layer_Name" at 577,-858.49 h60
Top Solder:
  text ".Layer_Name" at 577,-858.49 h60
  text ".Layer_Name" at 577,-858.49 h60
Solder Side:
  text ".Layer_Name" at 577,-858.49 h60
Drill Guide:
  text ".Layer_Name" at 577,-858.49 h60
Mechanical 1:
  the board outline again, w10
  text ".Layer_Name" at 577,-858.49 h60
Mechanical 2:
  rectangle: 0,-275 125,-150
  rectangle: 125,-400 500,-275
  lines w7: 0,-275 1000,-275 ; 125,-400 125,-150 ; 250,-400 250,-150 ; 500,-400 500,-150 ; 750,-400 750,-150 ; 0,-400 1000,-400 1000,-150 0,-150 0,-400
  text ".Layer_Name" at 577,-858.49 h60
Mechanical 3:
  text ".Layer_Name" at 577,-858.49 h60
Mechanical 4:
  text ".Layer_Name" at 577,-858.49 h60
Mechanical 5:
  lines w10: -292,-930.17 6308,-930.17 ; -292,-726.83 6310,-726.83 ; -292,-523.5 -292,-1133.5 3713,-1133.5 6310,-1133.5 6310,-523.5 -291.5,-523.5 -291.5,-1133.5 1284,-1133.5 ; 2173,-1133.5 2173,-523.5 ; 3440,-726.83 3440,-523.5 ; 4280,-726.83 4280,-523.5 ; 4902,-1140 4902,-937.17
  text "COMPONENTS MARKED 'DNP' SHOULD NOT BE POPULATED." at 1153.5,-318.5 h60
  text "ASSEMBLY VARIANT:" at 1153,-434 h60
  text ".VariantName" at 2189,-434 h60
  text "PCB VIEWED FROM TOP SIDE" at -228.5,-655.67 h60
  text "BOARD #:" at 2248,-655.67 h60
  text ".PRJ_Number" at 2793.5,-655.67 h60
  text "REV:" at 3638,-655.67 h60
  text ".PCB_Rev" at 3929.5,-655.67 h60
  text "SVN REV:" at 4476,-655.67 h60
  text ".VersionControl_RevNumber" at 4982,-655.67 h60
  text "TID #:" at 2248,-859 h60
  text ".TID" at 2793.5,-859 h60
  text "PLOT NAME =" at -228.5,-1064.34 h60
  text ".plot_File_Name" at 577,-1064.34 h60
  text "GENERATED    :" at 2250,-1064.34 h60
  text ".Print_Date" at 3119.5,-1064.34 h60
  text ".Print_Time" at 3848.5,-1064.34 h60
  text "TEXAS INSTRUMENTS" at 5113,-1064.34 h60
Mechanical 6:
  lines w10: -292.5,-727.33 6309.5,-727.33 ; -290.5,-930.67 6309.5,-930.67 ; 1115.5,-1140.5 1115.5,-937.67 ; 1737.5,-727.33 1737.5,-524 ; 2577.5,-727.33 2577.5,-524 ; 3844.5,-1134 3844.5,-524 ; 4733.5,-1134 6309,-1134 6309,-524 -292.5,-524 -292.5,-1134 2304.5,-1134 6309.5,-1134 6309.5,-524
  text "COMPONENTS MARKED 'DNP' SHOULD NOT BE POPULATED." at 6102,-318 h60
  text ".VariantName" at 5058,-434 h60
  text "ASSEMBLY VARIANT:" at 6097,-434 h60
  text ".VersionControl_RevNumber" at 1035.5,-656.17 h60
  text "SVN REV:" at 1541.5,-656.17 h60
  text ".PCB_Rev" at 2088,-656.17 h60
  text "REV:" at 2379.5,-656.17 h60
  text ".PRJ_Number" at 3224,-656.17 h60
  text "BOARD #:" at 3769.5,-656.17 h60
  text "PCB VIEWED FROM BOTTOM SIDE" at 6246,-656.17 h60
  text ".TID" at 3224,-859.5 h60
  text "TID #:" at 3769.5,-859.5 h60
  text "TEXAS INSTRUMENTS" at 904.5,-1064.84 h60
  text ".Print_Time" at 2169,-1064.84 h60
  text ".Print_Date" at 2898,-1064.84 h60
  text "GENERATED    :" at 3767.5,-1064.84 h60
  text ".plot_File_Name" at 5440.5,-1064.84 h60
  text "PLOT NAME =" at 6246,-1064.84 h60
Mechanical 9:
  drawing of 57 lines, arcs and shapes, not listed
  text "1" at 739.84,8036.5 h70
  text "2" at 3235.5,8036.5 h70
  text "3" at 5724.84,8036.5 h70
  text "4" at 8231.51,8036.5 h70
  text "5" at 10730.5,8036.5 h70
  text "6" at 13235.5,8036.5 h70
  text "A" at -416.5,6893.5 h70
  text "A" at 14383.5,6893.5 h70
  text "B" at -416.5,4513.5 h70
  text "B" at 14383.5,4513.5 h70
  text "C" at -416.5,2138.5 h70
  text "C" at 14383.5,2138.5 h70
  text "PROJECT TITLE:" at 11343.5,277.5 h45
  text ".PRJ_Title" at 11393.5,144.17 h70
  text "DESIGNED FOR:" at 11343.5,-23.5 h45
  text ".PRJ_Customer" at 11393.5,-163.5 h70
  text "D" at -416.5,-231.5 h70
  text "D" at 14383.5,-231.5 h70
  text "FILE NAME:" at 11343.5,-323.5 h45
  text ".PCB_File_Name_No_Path" at 11393.5,-443.5 h70
  text "Texas Instruments (TI) and/or its licensors do not warrant the accuracy or completeness of this specification" at 6374,-605.34 h45
  text "ENGINEER:" at 11343.5,-613.5 h45
  text "LAYOUT BY:" at 12848.5,-613.5 h45
  text "or any information contained therein. TI and/or its licensors do not warrant that this design will meet" at 6329.01,-718 h45
  text ".PRJ_Engineer" at 11393.5,-768.49 h70
  text ".PCB_Layout" at 12899,-768.49 h70
  text "the specifications, will be suitable for your application or fit for any particular purpose, or will operate in" at 6329.01,-830.67 h45
  text ".Layer_Name" at 577,-858.49 h60
  text "ALTIUM DESIGNER VERSION:" at 12848.5,-923.5 h45
  text "an implementation. TI and/or its licensors do not warrant that the design is production worthy. You should" at 6329.01,-943.33 h45
  text "completely validate and test your design implementation to confirm the system functionality for your application." at 6374,-1056 h45
  text ".print_Scale" at 11393.5,-1056.83 h70
  text ".Application_BuildNumber" at 12899,-1056.83 h70
  text "1" at 739.84,-1263.5 h70
  text "2" at 3235.5,-1263.5 h70
  text "3" at 5724.84,-1263.5 h70
  text "4" at 8231.51,-1263.5 h70
  text "5" at 10730.5,-1263.5 h70
  text "6" at 13235.5,-1263.5 h70
Mechanical 10:
  drawing of 189 lines, arcs and shapes, not listed
  text "DESIGN INFORMATION" at 12381.02,6028 h60
  text "MIN. TRACK WIDTH:" at 11736.46,5848 h60
  text "8" at 12832.7,5848 h60
  text "MIL" at 12987.46,5848 h60
  text "MIN. CLEARANCE:" at 11736.46,5716 h60
  text "0.2" at 12772.7,5716 h60
  text "mm" at 12987.46,5716 h60
  text "MIN. VIA PAD SIZE:" at 11736.46,5584 h60
  text "24" at 12802.71,5584 h60
  text "MIL" at 12987.46,5584 h60
  text "0.05mm (2MIL)" at 12431.46,5442.29 h60
  text "MINIMUM ANNULAR RING" at 11407.23,5438 h60
  text "EXTERNAL" at 13139.46,5438 h60
  text "PER" at 11607.23,5320 h60
  text "IPC-D-275 CLASS 2 LEVEL C" at 11827.23,5320 h60
  text "MIL, HOLES" at 13315.46,5207.71 h60
  text "+/-" at 12923,5207 h60
  text "+/-" at 13777,5207 h60
  text "REGISTRATION TOLERANCES:" at 11407.23,5202 h60
  text "METAL" at 12607,5202 h60
  text "5" at 13183.2,5202 h60
  text "3" at 14016.2,5202 h60
  text "MIL" at 14132.46,5202 h60
  text "+/-" at 13777,5089 h60
  text "HOLE SIZE TOLERANCE (UNLESS OTHERWISE SPECIFIED):" at 11407.23,5084 h60
  text "3" at 14016.2,5084 h60
  text "MIL" at 14132.46,5084 h60
  text "MATERIAL:" at 11332.46,4874.54 h60
  text "FR-4 High Tg" at 12318.9,4734.21 h60
  text "FR-408" at 11753.46,4725.64 h60
  text "OTHER" at 13241.46,4725.64 h60
  text "X" at 12164,4722 h60
  text "62 MIL (1.6mm) +/-10%" at 12073.56,4562.92 h60
  text "THICKNESS:" at 11407.23,4558.64 h60
  text "X" at 11945.4,4558.64 h60
  text "OTHER" at 13358.46,4558.64 h60
  text "TOLERANCE:" at 11407.23,4400.64 h60
  text "X" at 12246.53,4400.64 h60
  text "ANSI IPC-6012 TYPE 3 CLASS 2" at 12433.48,4400.64 h60
  text "OTHER +/-" at 12433.46,4244.64 h60
  text "BOW & TWIST:" at 11407.23,4087.64 h60
  text "X" at 12246.53,4087.64 h60
  text "ANSI IPC-6012 TYPE 3 CLASS 2" at 12433.48,4087.64 h60
  text "OTHER +/-" at 12433.46,3929.13 h60
  text "DRILLING:" at 11332.46,3790.64 h60
  text "REFERENCE:" at 11407.23,3673.64 h60
  text "X" at 12055.46,3673.64 h60
  text "AS SHOWN" at 12242.46,3673.64 h60
  text "X" at 12956.46,3673.64 h60
  text "NC_DRILL FILES" at 13093.46,3673.64 h60
  text "PTH MIN COPPER THICKNESS:" at 11407.23,3515.64 h60
  text "X" at 12757.46,3515.64 h60
  text "1MIL" at 12894.46,3515.64 h60
  text "OTHER" at 13391.46,3515.64 h60
  text "BOARD FINISH:" at 11332.46,3356.64 h60
  text "SILKSCREEN:" at 11487.68,3238.64 h60
  text "X" at 12436.46,3238.64 h60
  text "TOP" at 12562.46,3238.64 h60
  text "X" at 12946.46,3238.64 h60
  text "BOTTOM" at 13073.46,3238.64 h60
  text "SILKSCREEN COLOR:" at 11487.68,3071.64 h60
  text "X" at 12435.42,3071.64 h60
  text "WHITE" at 12562.46,3071.64 h60
  text "OTHER" at 13073.46,3071.64 h60
  text "X" at 12566.42,2912.44 h60
  text "GREEN" at 12693.46,2912.44 h60
  text "OTHER" at 13311.46,2912.44 h60
  text "SOLDER RESIST COLOR:" at 11487.68,2901.64 h60
  text "X" at 12566.42,2742.44 h60
  text "MATTE" at 12693.46,2742.44 h60
  text "SEMI-GLOSS" at 13311,2741.8 h60
  text "IMMERSION GOLD (ENIG)" at 12393.46,2553.92 h60
  text "ENEPIG" at 13731,2550.64 h60
  text "SURFACE FINISH:" at 11332.46,2549.64 h60
  text "X" at 12206.51,2549.64 h60
  text "IMM. TIN/SILVER OR EQUIV" at 11662,2392.64 h60
  text "OTHER" at 13093.46,2392.64 h60
  text "ARRAY/PANEL:" at 11332.46,2213.64 h60
  text "CUT AND TRIM PER M1 BOARD OUTLINE" at 12393.46,2209.35 h60
  text "N.C. ROUTE" at 12393.46,2057.64 h60
  text "X" at 13072.46,2057.64 h60
  text "V. SCORE" at 13259.46,2057.64 h60
  text "CERTIFICATION:" at 11332.46,1920.64 h60
  text "MATERIALS AND WORKMANSHIP FOR ALL PCBS" at 12057.46,1920.64 h60
  text "TO MEET OR EXCEED THE REQUIREMENTS OF:" at 12057.46,1822.64 h60
  text "X" at 11683.96,1686.13 h60
  text "ANSI IPC-A-600F CLASS ->" at 11822.96,1686.13 h60
  text "X" at 13462.02,1686.13 h60
  text "2" at 13580.96,1686.14 h60
  text "1" at 13265.96,1684.64 h60
  text "3" at 13934.96,1684.64 h60
  text "X" at 11686.02,1526.64 h60
  text "UL 94V-0" at 11822.96,1526.64 h60
  text "X" at 12498.02,1526.64 h60
  text "RoHS" at 12634.96,1526.64 h60
  text "OTHER" at 13279.36,1526.64 h60
  text "PER ORDER" at 13676.42,1526.64 h60
  text "ADDITIONAL REQUIREMENTS:" at 11332.46,1385.64 h60
  text "MICROSECTION:" at 11407.23,1270.64 h60
  text "YES" at 12312.96,1270.64 h60
  text "REQUIRED" at 13174.46,1114.49 h60
  text "BARE BOARD ELEC. TEST:" at 11407.23,1111.64 h60
  text "NONE" at 12712.96,1111.64 h60
  text "X" at 13047.46,1111.64 h60
  text "PER ORDER" at 13766.46,1111.64 h60
  text "MANUFACTURER'S UL:" at 11407.23,954.64 h60
  text "RAIL" at 12572.96,950.35 h60
  text "METAL" at 13064.77,950.35 h60
  text "X" at 13440,950 h60
  text "SILK" at 13576.46,950.35 h60
  text ".Layer_Name" at 577,-858.49 h60
Mechanical 11:
  lines w10: -292,-930.17 6308,-930.17 ; -292,-726.83 6310,-726.83 ; -292,-523.5 -292,-1133.5 3713,-1133.5 6310,-1133.5 6310,-523.5 -291.5,-523.5 -291.5,-1133.5 1284,-1133.5 ; 2173,-1133.5 2173,-523.5 ; 3440,-726.83 3440,-523.5 ; 4280,-726.83 4280,-523.5 ; 4902,-1140 4902,-937.17
  text "ALL ARTWORK VIEWED FROM TOP SIDE" at -228.5,-655.67 h60
  text "BOARD #:" at 2248,-655.67 h60
  text ".PRJ_Number" at 2793.5,-655.67 h60
  text "REV:" at 3638,-655.67 h60
  text ".PCB_Rev" at 3929.5,-655.67 h60
  text "SVN REV:" at 4476,-655.67 h60
  text ".VersionControl_RevNumber" at 4982,-655.67 h60
  text "LAYER NAME =" at -228.5,-858.49 h60
  text "TID #:" at 2248,-859 h60
  text ".TID" at 2793.5,-859 h60
  text "PLOT NAME =" at -228.5,-1064.34 h60
  text ".plot_File_Name" at 577,-1064.34 h60
  text "GENERATED    :" at 2250,-1064.34 h60
  text ".Print_Date" at 3119.5,-1064.34 h60
  text ".Print_Time" at 3848.5,-1064.34 h60
  text "TEXAS INSTRUMENTS" at 5113,-1064.34 h60
Mechanical 12:
  drawing of 527 lines, arcs and shapes, not listed
  text "Layer" at 8541.2,7700 h60
  text "Name" at 8951.11,7700 h60
  text "Material" at 9880.85,7700 h60
  text "Thickness" at 10740.62,7700 h60
  text "Constant" at 11390.46,7700 h60
  text "Board Layer Stack" at 11960.32,7700 h60
  text "Board Layer Stack" at 13080,7700 h60
  text "1" at 8541.2,7580 h60
  text "Top Overlay" at 8951.11,7580 h60
  text "2" at 8541.2,7460 h60
  text "Top Solder" at 8951.11,7460 h60
  text "Solder Resist" at 9880.85,7460 h60
  text "0.40mil" at 10740.62,7460 h60
  text "3.5" at 11390.46,7460 h60
  text "3" at 8541.2,7340 h60
  text "Top Layer" at 8951.11,7340 h60
  text "Copper" at 9880.85,7340 h60
  text "2.80mil" at 10740.62,7340 h60
  text "4" at 8541.2,7220 h60
  text "Dielectric" at 8951.11,7220 h60
  text "FR-4" at 9880.85,7220 h60
  text "12.00mil" at 10740.62,7220 h60
  text "4.2" at 11390.46,7220 h60
  text "5" at 8541.2,7100 h60
  text "Mid Layer" at 8951.11,7100 h60
  text "Copper" at 9880.85,7100 h60
  text "2.80mil" at 10740.62,7100 h60
  text "6" at 8541.2,6980 h60
  text "Dielectric" at 8951.11,6980 h60
  text "FR-4" at 9880.85,6980 h60
  text "34.00mil" at 10740.62,6980 h60
  text "4.2" at 11390.46,6980 h60
  text "7" at 8541.2,6860 h60
  text "GND Layer" at 8951.11,6860 h60
  text "Copper" at 9880.85,6860 h60
  text "2.80mil" at 10740.62,6860 h60
  text "8" at 8541.2,6740 h60
  text "Dielectric" at 8951.11,6740 h60
  text "FR-4" at 9880.85,6740 h60
  text "12.00mil" at 10740.62,6740 h60
  text "4.2" at 11390.46,6740 h60
  text "9" at 8541.2,6620 h60
  text "Bottom Layer" at 8951.11,6620 h60
  text "Copper" at 9880.85,6620 h60
  text "2.80mil" at 10740.62,6620 h60
  text "10" at 8541.2,6500 h60
  text "Solder Side" at 8951.11,6500 h60
  text "Solder Resist" at 9880.85,6500 h60
  text "0.40mil" at 10740.62,6500 h60
  text "3.5" at 11390.46,6500 h60
  text "11" at 8541.2,6380 h60
  text "Bottom Overlay" at 8951.11,6380 h60
  text ".Layer_Name" at 577,-858.49 h60
Mechanical 13:
  text ".Layer_Name" at 577,-858.49 h60
Mechanical 14:
  text ".Layer_Name" at 577,-858.49 h60
Mechanical 15:
  text ".Layer_Name" at 577,-858.49 h60
Mechanical 16:
  text ".Layer_Name" at 577,-858.49 h60
Drill Drawing:
  lines w10: 5156.09,4312.74 5183.72,4326.55 5211.34,4312.74 5197.53,4340.36 5211.34,4367.99 5183.72,4354.18 5156.09,4367.99 5169.9,4340.36 5156.09,4312.74 ; 5156.09,4437.06 5156.09,4450.87 5169.9,4464.68 5156.09,4478.5 5156.09,4492.31 5169.9,4492.31 5183.72,4478.5 5197.53,4492.31 5211.34,4492.31 5211.34,4478.5 5197.53,4464.68 5211.34,4450.87 5211.34,4437.06 5197.53,4437.06 5183.72,4450.87 5169.9,4437.06 5156.09,4437.06 ; 5156.09,4561.38 5211.34,4561.38 5211.34,4616.63 5156.09,4616.63 5156.09,4561.38 ; 5156.09,4699.51 5169.9,4699.51 5169.9,4685.7 5197.53,4685.7 5197.53,4699.51 5211.34,4699.51 5211.34,4727.14 5197.53,4727.14 5197.53,4740.95 5169.9,4740.95 5169.9,4727.14 5156.09,4727.14 5156.09,4699.51 ; 5156.09,4865.27 5211.34,4865.27 5183.72,4810.02 5156.09,4865.27 ; 5156.09,4948.15 5169.9,4948.15 5169.9,4934.34 5197.53,4934.34 5197.53,4948.15 5211.34,4948.15 5211.34,4975.78 5197.53,4975.78 5197.53,4989.59 5169.9,4989.59 5169.9,4975.78 5156.09,4975.78 5156.09,4948.15 ; 5156.09,5058.66 5183.72,5072.47 5211.34,5058.66 5197.53,5086.28 5211.34,5113.91 5183.72,5100.1 5156.09,5113.91 5169.9,5086.28 5156.09,5058.66 ; 5167.14,4953.67 5175.43,4953.67 5175.43,4945.39 5192.01,4945.39 5192.01,4953.67 5200.29,4953.67 5200.29,4970.25 5192.01,4970.25 5192.01,4978.54 5175.43,4978.54 5175.43,4970.25 5167.14,4970.25 5167.14,4953.67 ; 5167.14,5069.71 5183.72,5077.99 5200.29,5069.71 5192.01,5086.28 5200.29,5102.86 5183.72,5094.57 5167.14,5102.86 5175.43,5086.28 5167.14,5069.71
  lines w12: 5106,4275.44 8337.49,4275.44 ; 5106,5145.68 8337.49,5145.68 ; 5443.86,4151.12 5443.86,5270 ; 5775.86,4151.12 5775.86,5270 ; 6412.43,4151.12 6412.43,5270 ; 6671.57,4151.12 6671.57,5270 ; 7046.72,4151.12 7046.72,5270 ; 7771.05,4151.12 7771.05,5270 ; 5106,4151.12 8337.49,4151.12 8337.49,5270 5106,5270 5106,4151.12
  text "Symbol" at 5180.59,5182.98 h72
  text "Quantity" at 5481.16,5182.98 h72
  text "Finished Hole Size" at 5813.16,5182.98 h72
  text "Plated" at 6449.72,5182.98 h72
  text "Hole Type" at 6708.86,5182.98 h72
  text "Drill Layer Pair" at 7084.02,5182.98 h72
  text "Hole Tolerance" at 7808.35,5182.98 h72
  text "355" at 5481.16,5058.66 h60
  text "10.00mil (0.254mm)" at 5813.16,5058.66 h60
  text "PTH" at 6449.72,5058.66 h60
  text "Round" at 6708.86,5058.66 h60
  text "Top Layer - Bottom Layer" at 7084.02,5058.66 h60
  text "4" at 5481.16,4934.34 h60
  text "12.99mil (0.330mm)" at 5813.16,4934.34 h60
  text "PTH" at 6449.72,4934.34 h60
  text "Round" at 6708.86,4934.34 h60
  text "Top Layer - Bottom Layer" at 7084.02,4934.34 h60
  text "7" at 5481.16,4810.02 h60
  text "20.00mil (0.508mm)" at 5813.16,4810.02 h60
  text "PTH" at 6449.72,4810.02 h60
  text "Round" at 6708.86,4810.02 h60
  text "Top Layer - Bottom Layer" at 7084.02,4810.02 h60
  text "4" at 5481.16,4685.7 h60
  text "35.43mil (0.900mm)" at 5813.16,4685.7 h60
  text "PTH" at 6449.72,4685.7 h60
  text "Round" at 6708.86,4685.7 h60
  text "Top Layer - Bottom Layer" at 7084.02,4685.7 h60
  text "1" at 5481.16,4561.38 h60
  text "40.00mil (1.016mm)" at 5813.16,4561.38 h60
  text "PTH" at 6449.72,4561.38 h60
  text "Round" at 6708.86,4561.38 h60
  text "Top Layer - Bottom Layer" at 7084.02,4561.38 h60
  text "5" at 5481.16,4437.06 h60
  text "62.99mil (1.600mm)" at 5813.16,4437.06 h60
  text "PTH" at 6449.72,4437.06 h60
  text "Round" at 6708.86,4437.06 h60
  text "Top Layer - Bottom Layer" at 7084.02,4437.06 h60
  text "4" at 5481.16,4312.74 h60
  text "140.00mil (3.556mm)" at 5813.16,4312.74 h60
  text "PTH" at 6449.72,4312.74 h60
  text "Round" at 6708.86,4312.74 h60
  text "Top Layer - Bottom Layer" at 7084.02,4312.74 h60
  text "380 Total" at 5481.16,4188.42 h60
  text ".Layer_Name" at 577,-858.49 h60

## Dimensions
2240,1390 to 2240,4080 on Mechanical 1
2240,1390 to 4760,1390 on Mechanical 1
0,-400 to 1000,-400 on Mechanical 2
